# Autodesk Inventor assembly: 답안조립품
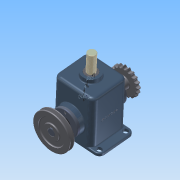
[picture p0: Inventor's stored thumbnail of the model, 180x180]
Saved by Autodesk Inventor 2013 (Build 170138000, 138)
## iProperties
Created: 2015-03
Part Number: 답안조립품
Document SubType Name: Assembly
Designer: Administrator
Mass: 8579 g
Surface Area: 4386.44 cm^2
Volume: 1982.5 cm^3
Density: 4.32736 g/cm^3
Author: Administrator
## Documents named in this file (15)
- C:\Documents and Settings\Administrator\바탕 화면\350305V1017\답안조립품.iam
- C:\Documents and Settings\Administrator\바탕 화면\350305V1017\본체.ipt
- C:\Documents and Settings\Administrator\바탕 화면\350305V1017\오일실.ipt
- C:\Documents and Settings\Administrator\바탕 화면\350305V1017\커버.ipt
- C:\Documents and Settings\Administrator\바탕 화면\350305V1017\M4x0.5.ipt
- C:\Documents and Settings\Administrator\바탕 화면\350305V1017\베어링 6205.ipt
- C:\Documents and Settings\Administrator\바탕 화면\350305V1017\체인 스프로킷.ipt
- C:\Documents and Settings\Administrator\바탕 화면\350305V1017\편심축.ipt
- C:\Documents and Settings\Administrator\바탕 화면\350305V1017\V-벨트풀리.ipt
- C:\Documents and Settings\Administrator\바탕 화면\350305V1017\멈춤링.ipt
- C:\Documents and Settings\Administrator\바탕 화면\350305V1017\멈춤나사 M5x0.5.ipt
- C:\Documents and Settings\Administrator\바탕 화면\350305V1017\키 8x8.ipt
- C:\Documents and Settings\Administrator\바탕 화면\350305V1017\슬라이드.ipt
- C:\Documents and Settings\Administrator\바탕 화면\350305V1017\부시.ipt
- C:\Documents and Settings\Administrator\바탕 화면\350305V1017\7-가변스프링.ipt
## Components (9 placed, 4 different names)
1. 5-체인 스프로킷:1 — 플러쉬:2, 각도:3
2. V-벨트풀리:1 — 플러쉬:3, 각도:4
3. 7-가변스프링:1
4. M4x0.5:1
5. M4x0.5:2
6. M4x0.5:3
7. M4x0.5:4
8. M4x0.5:5
9. M4x0.5:6
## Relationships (4: Flush 2, Angle 2)
- 플러쉬:2 [Flush]: 5-체인 스프로킷:1
- 각도:3 [Angle]: 5-체인 스프로킷:1
- 플러쉬:3 [Flush]: V-벨트풀리:1
- 각도:4 [Angle]: V-벨트풀리:1
